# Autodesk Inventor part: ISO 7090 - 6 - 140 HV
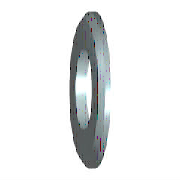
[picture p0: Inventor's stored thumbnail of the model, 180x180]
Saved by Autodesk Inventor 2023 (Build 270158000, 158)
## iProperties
Created: 2015-02
Part Number: ISO 7090 - 6 - 140 HV
Material: Stainless Steel
Description: Plain washers, charmfered - Normal series - Product grade A
Document SubType Name: Modeling
Standard: ISO 7090
Designer: Cadskolen
Standard Revision: Second edition 2000-06-01
Standards Organization: ISO
Language: en-US
Size Designation: 6 - 140 HV
Categories: <MemberInstance><Categories><Category DisplayName="Fasteners" InternalName="e4da775c-781d-43d5-af7c-5136215cf5a6" Mnemonic="FSTN"><Category DisplayName="Washers
Density: 8 g/cm^3
Appearance: Semi-Polished
Mass: 0.943651 g
Surface Area: 2.35844 cm^2
Volume: 0.117956 cm^3
IsCustomPart: 0
Author: Cadskolen
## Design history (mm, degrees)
sketch "Sketch"
  geometry: C1 r 6 at (0, 0); C2 r 3.2 at (0, 0); 1 further point
  constraints: 2 centre point, 2 coincident
  dimensions: "d0" = 6.4 diameter of C2 (= SD1); "d1" = 12 diameter of C1 (= SD2)
extrude "Body" new body sketch "Sketch" distance "d2" = 1.6 (= SD); taper "d3" = 0 deg
workaxis "Work Axis1"
workplane "Work Plane1"
body "Solid1"
chamfer "Chamfer" distance "d4" = 0.8 (= PHH); stored, may be unused: angle "d5" = 45 deg, second distance "d8" = 0.8 (= PHH)
other parameters: "SD1" = 6.4 [user parameter; used in 1 equation term], "SD2" = 12 [user parameter; used in 1 equation term], "SD" = 1.6 [user parameter; used in 1 equation term], "PHH" = 0.8 [user parameter; used in 2 equation terms], "FAWI" = 45 deg [user parameter], "d6" = 0, "d7" = 0, "d9" = 0, "d10" = 0, "NND" = 6 [user parameter]
